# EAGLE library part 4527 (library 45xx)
BCD rate MULTIPLIER
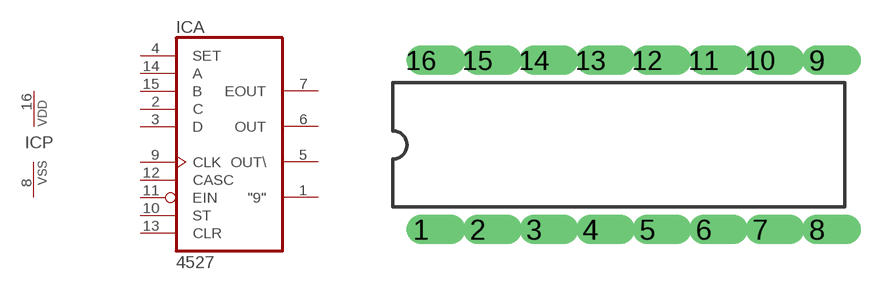
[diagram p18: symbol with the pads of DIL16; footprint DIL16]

Designator prefix IC; gates A=4527 P=PWRN

## 4527N  [DIL16]
1  A:"9"  out
2  A:C  in
3  A:D  in
4  A:SET  in
5  A:OUT\  out
6  A:OUT  out
7  A:EOUT  out
8  P:VSS  pwr
9  A:CLK  in
10  A:ST  in
11  A:EIN  in
12  A:CASC  in
13  A:CLR  in
14  A:A  in
15  A:B  in
16  P:VDD  pwr

## Footprint DIL16 (pad centres in mm)
Dual In Line
drill 0.813 offset: 1 -8.89,-3.81; 2 -6.35,-3.81; 3 -3.81,-3.81; 4 -1.27,-3.81; 5 1.27,-3.81; 6 3.81,-3.81; 7 6.35,-3.81; 8 8.89,-3.81; 9 8.89,3.81; 10 6.35,3.81; 11 3.81,3.81; 12 1.27,3.81; 13 -1.27,3.81; 14 -3.81,3.81; 15 -6.35,3.81; 16 -8.89,3.81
